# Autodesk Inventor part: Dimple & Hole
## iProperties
Shininess: 64.0
Length Units: 11269
Angle Units: 11279
Time Units: 11290
Mass Units: 11283
Length Display Precision: 3
Angle Display Precision: 2
Compacted: True
Part Number: Dimple & Hole
Document SubType Name: Sheet Metal
Created: 2003-04
Designer: Andy
Density: 0.0
Volumn: 0.0
Area: 0.0
PropertySet Name: Model Information
Control State: 0
Master: False
Checked Out: False
Author: Andy Marshall
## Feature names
1. Revolution1
2. Revolution2
3. Hole1
4. Plate1
